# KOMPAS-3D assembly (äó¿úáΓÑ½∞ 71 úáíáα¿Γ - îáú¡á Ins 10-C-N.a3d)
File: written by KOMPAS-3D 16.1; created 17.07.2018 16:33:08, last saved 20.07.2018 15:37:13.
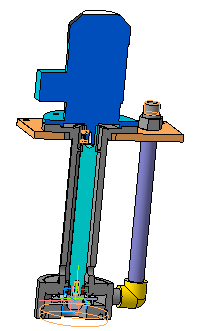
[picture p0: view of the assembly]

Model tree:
1. Булева операция:11
2. Булева операция:12
3. Массив по образцу:1  (2 pattern instances)
4. Сечение поверхностью:6  (labels: Полипропилен  ГОСТ 26996-86)
     Расстояние = 1.5; Расстояние = -2.5

Referenced files in Z:\Магна\Магна Ins\Магна ins 10\М10-00.00.000\3Д\: М10-00.00.002 - Крышка.m3d, М10-00.00.001 - Импеллер Магна10.m3d, М10-00.00.003 - Защитная втулка.m3d, Двигатель 80 габарит - Корпус.a3d, М10-00.15.001-01 - Вал.m3d, М10-00.15.002 - Фиксатор.m3d, М10-00.15.002 - Фиксатор.cdw
Referenced files in Z:\1 ПКИ 3D\РТИ\Кольца уплотнительные  плоские\: Кольцо плоское уплотнительное 10-23-25 EPDM.m3d
Referenced files in Z:\АкваProf\АкваProf 190\3Д модель\: М10А-00.00.003 - Втулка ответная.m3d
Referenced files in Z:\1 ПКИ 3D\Двигатели\АИР\: Электродвигатель 3ф. АИР 71А2 380В 0,75кВт 3000об_мин 3081 DRIVE IEK.m3d
Referenced files in C:\Program Files\ASCON\KOMPAS-3D V16\Libs\PartLib\DATA\vault\Methods\Kompas\3D\: PLib_Screw_GOST_8878-84_900.m3d
Referenced files: graphic.tdp
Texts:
  Двигатель 71 габарит
  @100~)2xA3
  (+) М10-00.20.000 Корпус
  (+) М10-00.00.002 Крышка
  Импеллер Магна10
  (-) М10-00.00.001 Импеллер Магна10
  Кольцо плоское уплотнительное
  Кольцо плоское уплотнительное / 10-23-25 EPDM
  (-) Кольцо плоское уплотнительное / 10-23-25 EPDM
  (-) М10-00.00.003 Защитная втулка
  (-) М10А-00.00.003-01 Втулка ответная
  (-) М10-00.15.001 Вал
  Электродвигатель 3ф. АИР 71А2
  380В 0,75кВт 3000 об/мин 3081 DRIVE IEK
  арт.DRV071-A2-000-8-3030
  Электродвигатель 3ф. АИР 71А2 / 380В 0,75кВт 3000 об/мин 3081 DRIVE IEK / арт.DRV071-A2-000-8-3030
  IP55
  (+) Электродвигатель 3ф. АИР 71А2 380В 0,75кВт 3000об/мин 3081 DRIVE IEK
  (+) М10-00.15.002 Фиксатор
  Сталь 12Х18Н10Т ГОСТ 5632-72
  Винт А.М6-6gx16.21.12Х18Н10Т ГОСТ 8878-93
  Крепежное изделие ГОСТ
  (-) Винт А.М6-6gx16.21.12Х18Н10Т ГОСТ 8878-93 (1)
  Магна Ins 10-C-N
  ГОСТ 8878-93
  А.М6-6gx16.21.12Х18Н10Т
